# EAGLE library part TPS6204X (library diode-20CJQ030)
Ti's TPS6204x 1.2 A/1.25 MHz, HIGH-EFFICIENCY STEP-DOWN CONVERTER Description: The TPS6204x family of devices are high efficiency synchronous step-down dc-dc converters optimized for battery powered portable applications. The devices are ideal for portable applications powered by a single Li-Ion battery cell or by 3-cell NiMH/NiCd batteries. With an output voltage range from 6.0 V down to 0.7 V, the devices support low voltage DSPs and processors in PDAs, pocket PCs, as well as notebooks and subnotebook computers. The TPS6204x operates at a fixed switching frequency of 1.25 MHz and enters the power save mode operation at light load currents to maintain high efficiency over the entire load current range. For low noise applications, the devices can be forced into fixed frequency PWM mode by pulling the MODE pin high. The TPS6204x supports up to 1.2-A load current. Features: Up to 95% Conversion Efficiency Typical Quiescent Current: 18 µA Load Current: 1.2 A Operating Input Voltage Range: 2.5 V to 6.0 V Switching Frequency: 1.25 MHz Adjustable and Fixed Output Voltage Power Save Mode Operation at Light load Currents 100% Duty Cycle for Lowest Dropout Internal Softstart Dynamic Output Voltage Positioning Thermal Shutdown Short-Circuit Protection 10 Pin MSOP PowerPad? Package 10 Pin QFN 3 X 3 mm Package Applications: PDA, Pocket PC and Smart Phones USB Powered Modems CPUs and DSPs PC Cards and Notebooks xDSL Applications Standard 5-V to 3.3-V Conversion Please send any comments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
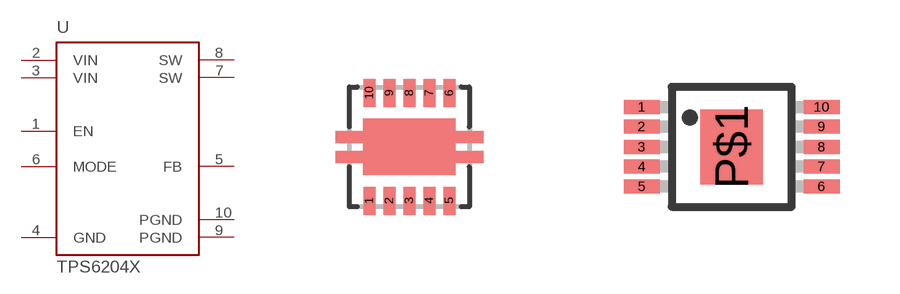
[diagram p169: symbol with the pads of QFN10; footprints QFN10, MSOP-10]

Designator prefix U

## TPS6204X-DRC  [QFN10]
1  EN  in
2  VIN  pwr
3  VIN  pwr
4  GND  pwr
5  FB
6  MODE  in
7  SW
8  SW
9  PGND  pwr
10  PGND  pwr

## TPS6204X-DGQ  [MSOP-10]
1  EN  in
2  VIN  pwr
3  VIN  pwr
4  GND  pwr
5  PGND  pwr
6  PGND  pwr
7  FB
8  MODE  in
9  SW
10  SW

## Footprint QFN10 (pad centres in mm)
QFN10 for Ti's TPS6204x
smd 0.3 x 0.7: 1 -1,-1.35; 2 -0.5,-1.35; 3 0,-1.35; 4 0.5,-1.35; 5 1,-1.35; 6 1,1.35; 7 0.5,1.35; 8 0,1.35; 9 -0.5,1.35; 10 -1,1.35

## Footprint MSOP-10 (pad centres in mm)
Ti's MSOP-10 with PowerPAD
smd 0.9 x 0.35: 1 -2.25,1; 2 -2.25,0.51; 3 -2.25,0; 4 -2.25,-0.49; 5 -2.25,-0.99; 6 2.25,-0.99; 7 2.25,-0.49; 8 2.25,0; 9 2.25,0.51; 10 2.25,1
smd 1.57 x 1.88: P$1 0,0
